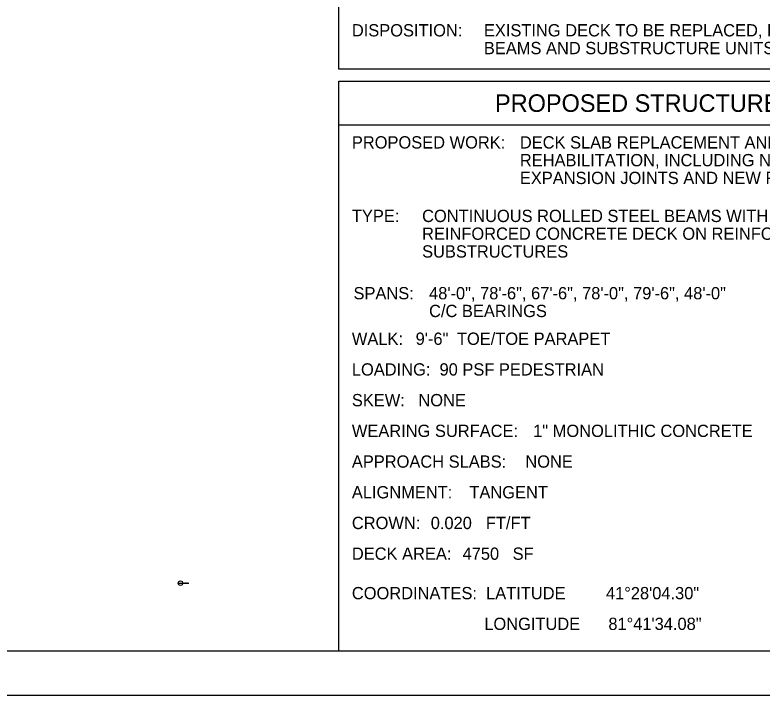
# Model space of a CAD drawing. Extents: x 58.8 to 101.8, y -10 to 13.1.
# Drawn here: x 79.85 to 88.36, y -8.86 to -1.11 of the extents above; entities that cross this region are included whole.
import ezdxf

# ---------------------------------------------------------------- set-up
doc = ezdxf.new("R2010")
doc.units = 0
for name, color, linetype in [('DT_X_Contour_Major', 7, 'Continuous'), ('DT_X_Contour_Minor', 7, 'Continuous'), ('DT_X_Spot_Elev', 7, 'Continuous'), ('DT_X_Triangles', 7, 'Continuous')]:
    doc.layers.add(name, color=color, linetype=linetype)

msp = doc.modelspace()

# ---------------------------------------------------------------- linework, layer by layer
at = {"layer": 'DT_X_Contour_Major'}
msp.add_line((90.7872, -2.3644), (83.5373, -2.3644), dxfattribs=at)
for points in [[(83.5373, 3.8856), (90.7872, 3.8856), (90.7872, -1.7288), (83.5373, -1.7288)], [(83.5373, -1.8644), (90.7872, -1.8644), (90.7872, -8.3619), (83.5373, -8.3619)]]:
    msp.add_lwpolyline(points, close=True, dxfattribs=at)
at = {"layer": 'DT_X_Contour_Minor'}
msp.add_lwpolyline([(58.7872, -8.8619), (92.7872, -8.8619), (92.7872, 13.1381), (58.7872, 13.1381)], close=True, dxfattribs=at)
at = {"layer": 'DT_X_Spot_Elev'}
msp.add_lwpolyline([(60.2872, 12.6381), (92.2872, 12.6381), (92.2872, -8.3619), (60.2872, -8.3619)], close=True, dxfattribs=at)
at = {"layer": 'DT_X_Triangles'}
for p, q in [((81.7086, -7.5869), (81.7606, -7.5869)), ((81.7348, -7.5869), (81.8305, -7.5869))]:
    msp.add_line(p, q, dxfattribs=at)
msp.add_circle((81.7346, -7.5869), 0.026, dxfattribs=at)

# ---------------------------------------------------------------- texts
at = {"layer": 'DT_X_Contour_Major'}
for s, height, p in [('DISPOSITION:', 0.14, (83.6873, -1.3542)), ('EXISTING DECK TO BE REPLACED, EXISTING STEEL ', 0.14, (85.1914, -1.3542)), ('BEAMS AND SUBSTRUCTURE UNITS TO REMAIN ', 0.14, (85.1914, -1.5567)), ('PROPOSED STRUCTURE', 0.2, (85.3182, -2.2144)), ('PROPOSED WORK:', 0.14, (83.6873, -2.6319)), ('DECK SLAB REPLACEMENT AND SUBSTRUCTURE', 0.14, (85.6008, -2.6319)), ('REHABILITATION, INCLUDING NEW STRIP SEAL', 0.14, (85.6008, -2.8344)), ('EXPANSION JOINTS AND NEW FENCE.', 0.14, (85.6008, -3.0369)), ('TYPE:', 0.14, (83.6873, -3.47)), ('CONTINUOUS ROLLED STEEL BEAMS WITH COMPOSITE ', 0.14, (84.4873, -3.47)), ('REINFORCED CONCRETE DECK ON REINFORCED CONCRETE ', 0.14, (84.4873, -3.6725)), ('SUBSTRUCTURES', 0.14, (84.4873, -3.875)), ('SPANS:', 0.14, (83.706, -4.3509)), ('48\'-0", 78\'-6", 67\'-6", 78\'-0", 79\'-6", 48\'-0" ', 0.14, (84.5668, -4.3509)), ('C/C BEARINGS', 0.14, (84.5668, -4.5534)), ('WALK:', 0.14, (83.6873, -4.87)), ('9\'-6"', 0.14, (84.4138, -4.87)), ('TOE/TOE PARAPET', 0.14, (84.8841, -4.87)), ('LOADING:  90 PSF PEDESTRIAN', 0.14, (83.6873, -5.22)), ('SKEW:', 0.14, (83.6873, -5.57)), ('NONE', 0.14, (84.445, -5.57)), ('WEARING SURFACE:', 0.14, (83.6873, -5.92)), ('1" MONOLITHIC CONCRETE', 0.14, (85.7526, -5.92)), ('APPROACH SLABS:', 0.14, (83.6873, -6.27)), ('NONE', 0.14, (85.6633, -6.27)), ('ALIGNMENT:', 0.14, (83.6873, -6.62)), ('TANGENT', 0.14, (85.0261, -6.62)), ('CROWN:', 0.14, (83.6873, -6.97)), ('0.020', 0.14, (84.5856, -6.97)), ('FT/FT', 0.14, (85.2134, -6.97)), ('DECK AREA:', 0.14, (83.6873, -7.32)), ('4750', 0.14, (84.9484, -7.32)), ('SF', 0.14, (85.5186, -7.32)), ('COORDINATES:  LATITUDE', 0.14, (83.6873, -7.77)), ('41°28\'04.30"', 0.14, (86.5818, -7.77)), ('                             LONGITUDE', 0.14, (83.6873, -8.12)), ('81°41\'34.08"', 0.14, (86.6091, -8.12))]:
    msp.add_text(s, height=height, dxfattribs=at).set_placement(p)
at = {"layer": 'DT_X_Triangles'}
for s, height, p in [('P.18', 0.00328, (81.7302, -7.5967)), ('1', 0.00328, (81.7338, -7.5803)), ('105793_SFN_1805495_SP001', 0.003281, (81.7672, -7.5803)), ('1:20', 0.00328, (81.7672, -7.5967))]:
    msp.add_text(s, height=height, dxfattribs=at).set_placement(p)

doc.saveas('drawing.dxf')
